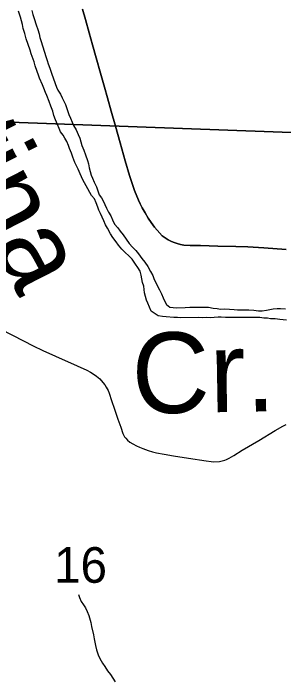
# Model space of a CAD drawing. Extents: x -3.3 to 34, y 0 to 56.8.
# Drawn here: x -0.926 to -0.609, y 31.042 to 31.825 of the extents above; entities that cross this region are included whole.
import ezdxf

# ---------------------------------------------------------------- set-up
doc = ezdxf.new("R2010")
doc.units = 0
for name, color, linetype in [('GM_X_Corporation', 7, 'Continuous'), ('GM_X_County_Road', 7, 'Continuous'), ('GM_X_Major_River', 7, 'Continuous'), ('GM_X_Major_River_Text', 7, 'Continuous'), ('GM_X_Section_Text', 7, 'Continuous'), ('GM_X_State_Route', 7, 'Continuous'), ('GM_X_Township_Road', 7, 'Continuous'), ('GT_Project_Soil_Layers', 7, 'Continuous')]:
    doc.layers.add(name, color=color, linetype=linetype)

msp = doc.modelspace()

# ---------------------------------------------------------------- linework, layer by layer
at = {"layer": 'GM_X_Corporation'}
for points in [[(-1.30168, 32.71458), (-0.28775, 32.6826), (-0.3225, 31.67471), (-1.33537, 31.71163)], [(-1.33537, 31.71163), (-0.3225, 31.67471), (-0.36109, 30.66979), (-1.36367, 30.70347)]]:
    msp.add_lwpolyline(points, close=True, dxfattribs=at)
at = {"layer": 'GM_X_County_Road'}
msp.add_lwpolyline([(-0.60551, 31.54726), (-0.63197, 31.54907), (-0.65072, 31.5503), (-0.66494, 31.55096), (-0.68607, 31.55138), (-0.70637, 31.55179), (-0.71846, 31.55203), (-0.72593, 31.55252), (-0.72972, 31.55318), (-0.73382, 31.55417), (-0.73736, 31.5554), (-0.7404, 31.55663), (-0.74443, 31.55868), (-0.74797, 31.56091), (-0.75117, 31.56337), (-0.75732, 31.56995), (-0.76041, 31.57368), (-0.76431, 31.57884), (-0.76786, 31.58425), (-0.77147, 31.59034), (-0.77468, 31.59609), (-0.77715, 31.60086), (-0.7792, 31.60529), (-0.78391, 31.61667), (-0.78742, 31.62725), (-0.78964, 31.63423), (-0.7948, 31.65124), (-0.80072, 31.67269), (-0.80624, 31.69216), (-0.81125, 31.7098), (-0.8157, 31.72547), (-0.81924, 31.73789), (-0.82392, 31.75453), (-0.82894, 31.77237), (-0.8332, 31.78752), (-0.83718, 31.80165), (-0.8416, 31.81737), (-0.84509, 31.82976)], dxfattribs=at)
at = {"layer": 'GM_X_Major_River'}
for points in [[(-0.77983, 31.52609), (-0.78253, 31.52985), (-0.78679, 31.53587), (-0.79064, 31.53999), (-0.79486, 31.54372), (-0.7987, 31.54785), (-0.80256, 31.55235), (-0.80526, 31.55611), (-0.80913, 31.56137), (-0.81222, 31.5655), (-0.81572, 31.57228), (-0.81806, 31.57642), (-0.82001, 31.58095), (-0.82392, 31.58963), (-0.82587, 31.5934), (-0.82706, 31.59718), (-0.82902, 31.60208), (-0.83098, 31.60661), (-0.83445, 31.61074), (-0.84067, 31.62204), (-0.84456, 31.6292), (-0.84769, 31.63599), (-0.85004, 31.64165), (-0.85394, 31.64957), (-0.8563, 31.65561), (-0.85788, 31.66052), (-0.86023, 31.6658), (-0.86142, 31.66958), (-0.86337, 31.67411), (-0.8657, 31.67788), (-0.86765, 31.68164), (-0.87073, 31.6854), (-0.87231, 31.68955), (-0.87426, 31.69408), (-0.87662, 31.69974), (-0.87858, 31.70465), (-0.87979, 31.70995), (-0.88214, 31.71561), (-0.88411, 31.72128), (-0.88686, 31.72807), (-0.88843, 31.73184), (-0.89039, 31.73675), (-0.89196, 31.74053), (-0.89548, 31.74845), (-0.89667, 31.75223), (-0.89824, 31.75638), (-0.90061, 31.76318), (-0.90181, 31.76772), (-0.90535, 31.77717), (-0.90655, 31.78132), (-0.91128, 31.79492), (-0.91251, 31.80098), (-0.91448, 31.80703), (-0.9153, 31.81157), (-0.9177, 31.82027), (-0.92006, 31.82707)], [(-0.90453, 31.82805), (-0.90333, 31.82313), (-0.90175, 31.8186), (-0.89937, 31.81104), (-0.8974, 31.80575), (-0.89581, 31.80046), (-0.895, 31.79629), (-0.89342, 31.79176), (-0.89183, 31.78647), (-0.88945, 31.77891), (-0.88787, 31.77399), (-0.88628, 31.76908), (-0.88547, 31.7653), (-0.88351, 31.76039), (-0.88114, 31.75321), (-0.87956, 31.74905), (-0.8772, 31.74225), (-0.87562, 31.7381), (-0.87406, 31.73432), (-0.87096, 31.72981), (-0.869, 31.72528), (-0.86511, 31.71775), (-0.86313, 31.7117), (-0.86115, 31.70603), (-0.8592, 31.7015), (-0.85724, 31.69697), (-0.85567, 31.69282), (-0.85256, 31.68793), (-0.85021, 31.68227), (-0.84826, 31.67812), (-0.84706, 31.67358), (-0.84587, 31.66942), (-0.84351, 31.66376), (-0.84155, 31.65847), (-0.83918, 31.65167), (-0.83799, 31.64789), (-0.83717, 31.64335), (-0.83597, 31.63881), (-0.83477, 31.63465), (-0.83321, 31.63088), (-0.83125, 31.62635), (-0.82852, 31.62107), (-0.82733, 31.61729), (-0.82536, 31.61163), (-0.82265, 31.60787), (-0.82032, 31.60372), (-0.81875, 31.59995), (-0.8168, 31.5958), (-0.81447, 31.59128), (-0.81175, 31.58676), (-0.80979, 31.58224), (-0.80744, 31.57695), (-0.8036, 31.57283), (-0.80051, 31.5687), (-0.79704, 31.56457), (-0.79355, 31.55931), (-0.79007, 31.55442), (-0.78622, 31.54992), (-0.78238, 31.54618), (-0.77929, 31.54204), (-0.77542, 31.53678), (-0.77157, 31.53228), (-0.76809, 31.5274), (-0.76497, 31.52137), (-0.76226, 31.51685), (-0.76107, 31.51307), (-0.75873, 31.50817), (-0.75445, 31.49988), (-0.75211, 31.49536), (-0.75014, 31.49045), (-0.74819, 31.4863), (-0.74624, 31.48253), (-0.74241, 31.47955), (-0.73862, 31.47922), (-0.73406, 31.47891), (-0.7242, 31.47904), (-0.7189, 31.4795), (-0.70828, 31.47965), (-0.70297, 31.47934), (-0.69691, 31.47942), (-0.69158, 31.47836), (-0.68665, 31.47805), (-0.68284, 31.47734), (-0.67792, 31.47741), (-0.66691, 31.47681), (-0.66274, 31.47649), (-0.65856, 31.47654), (-0.65363, 31.47624), (-0.64946, 31.47629), (-0.64377, 31.47599), (-0.63807, 31.47531), (-0.6339, 31.47537), (-0.6286, 31.47582), (-0.62104, 31.47745), (-0.61611, 31.4779), (-0.61232, 31.47795), (-0.60663, 31.47765)], [(-0.60531, 31.46438), (-0.61328, 31.46503), (-0.6186, 31.46571), (-0.62391, 31.46602), (-0.62771, 31.46673), (-0.63189, 31.46667), (-0.63645, 31.46736), (-0.64517, 31.46724), (-0.6501, 31.46755), (-0.66792, 31.4673), (-0.67285, 31.46724), (-0.67702, 31.46756), (-0.68196, 31.46787), (-0.68575, 31.46782), (-0.69029, 31.46737), (-0.69408, 31.46694), (-0.69977, 31.46724), (-0.70356, 31.46719), (-0.7085, 31.4675), (-0.72973, 31.4672), (-0.73353, 31.46753), (-0.7377, 31.46747), (-0.74681, 31.4681), (-0.75098, 31.46842), (-0.75593, 31.46949), (-0.75975, 31.47171), (-0.76434, 31.47469), (-0.7663, 31.4796), (-0.76826, 31.48412), (-0.76983, 31.4879), (-0.77222, 31.49621), (-0.77308, 31.50417), (-0.77428, 31.50833), (-0.7751, 31.51287), (-0.77591, 31.51704), (-0.77712, 31.52196), (-0.77983, 31.52609)]]:
    msp.add_lwpolyline(points, dxfattribs=at)
at = {"layer": 'GM_X_State_Route'}
msp.add_lwpolyline([(-0.84509, 31.82976), (-0.8416, 31.81737), (-0.83718, 31.80165), (-0.8332, 31.78752), (-0.82894, 31.77237), (-0.82392, 31.75453), (-0.81924, 31.73789), (-0.8157, 31.72547), (-0.81125, 31.7098), (-0.80624, 31.69216), (-0.80072, 31.67269), (-0.7948, 31.65124), (-0.78964, 31.63423), (-0.78742, 31.62725), (-0.78391, 31.61667), (-0.7792, 31.60529), (-0.77715, 31.60086), (-0.77468, 31.59609), (-0.77147, 31.59034), (-0.76786, 31.58425), (-0.76431, 31.57884), (-0.76041, 31.57368), (-0.75732, 31.56995), (-0.75117, 31.56337), (-0.74797, 31.56091), (-0.74443, 31.55868), (-0.7404, 31.55663), (-0.73736, 31.5554), (-0.73382, 31.55417), (-0.72972, 31.55318), (-0.72593, 31.55252), (-0.71846, 31.55203), (-0.70637, 31.55179), (-0.68607, 31.55138), (-0.66494, 31.55096), (-0.65072, 31.5503), (-0.63197, 31.54907), (-0.60551, 31.54726)], dxfattribs=at)
at = {"layer": 'GM_X_Township_Road'}
msp.add_lwpolyline([(-0.9409, 31.45356), (-0.91435, 31.43992), (-0.90292, 31.43416), (-0.8916, 31.42874), (-0.87654, 31.42191), (-0.85106, 31.41065), (-0.83996, 31.40563), (-0.83552, 31.4033), (-0.83114, 31.40055), (-0.82853, 31.3986), (-0.82468, 31.39527), (-0.82101, 31.39116), (-0.81872, 31.38818), (-0.81696, 31.38551), (-0.81474, 31.38155), (-0.81357, 31.37834), (-0.81079, 31.3699), (-0.80738, 31.3596), (-0.80334, 31.34794), (-0.80007, 31.33853), (-0.79752, 31.33118), (-0.79674, 31.32942), (-0.79544, 31.32717), (-0.79422, 31.32551), (-0.79211, 31.32335), (-0.78916, 31.32113), (-0.78564, 31.3189), (-0.78159, 31.31677), (-0.7781, 31.31513), (-0.77392, 31.31335), (-0.76795, 31.31117), (-0.76273, 31.30961), (-0.75811, 31.30848), (-0.74896, 31.30674), (-0.73796, 31.30489), (-0.72044, 31.3022), (-0.6998, 31.29902), (-0.69371, 31.29816), (-0.69047, 31.29793), (-0.68402, 31.29833), (-0.68086, 31.29897), (-0.67779, 31.2999), (-0.67568, 31.30073), (-0.67277, 31.30213), (-0.66713, 31.30548), (-0.65722, 31.31152), (-0.6379, 31.32302), (-0.61878, 31.33454), (-0.60971, 31.33958), (-0.60568, 31.34157)], dxfattribs=at)
at = {"layer": 'GT_Project_Soil_Layers'}
msp.add_lwpolyline([(-0.8497, 31.14214), (-0.84851, 31.13836), (-0.84655, 31.13383), (-0.84385, 31.13008), (-0.84152, 31.12631), (-0.83957, 31.12216), (-0.83761, 31.11726), (-0.83522, 31.10894), (-0.8344, 31.1044), (-0.83199, 31.09457), (-0.83117, 31.09002), (-0.83036, 31.08586), (-0.82955, 31.08207), (-0.82834, 31.07716), (-0.82636, 31.07111), (-0.82441, 31.06697), (-0.8213, 31.06132), (-0.8186, 31.05756), (-0.81549, 31.05229), (-0.81202, 31.04817), (-0.80931, 31.04365), (-0.80659, 31.03951)], dxfattribs=at)

# ---------------------------------------------------------------- texts
at = {"layer": 'GM_X_Major_River_Text'}
for s, height, rotation, p in [('tina', 0.094703, 297.00242, (-1.01174, 31.67189)), ('Cr.', 0.094702, 1.01042, (-0.78636, 31.35438))]:
    msp.add_text(s, height=height, rotation=rotation, dxfattribs=at).set_placement(p)
at = {"layer": 'GM_X_Section_Text'}
msp.add_text('16', height=0.041856, rotation=0.00001, dxfattribs=at).set_placement((-0.8784, 31.15578))

doc.saveas('drawing.dxf')
